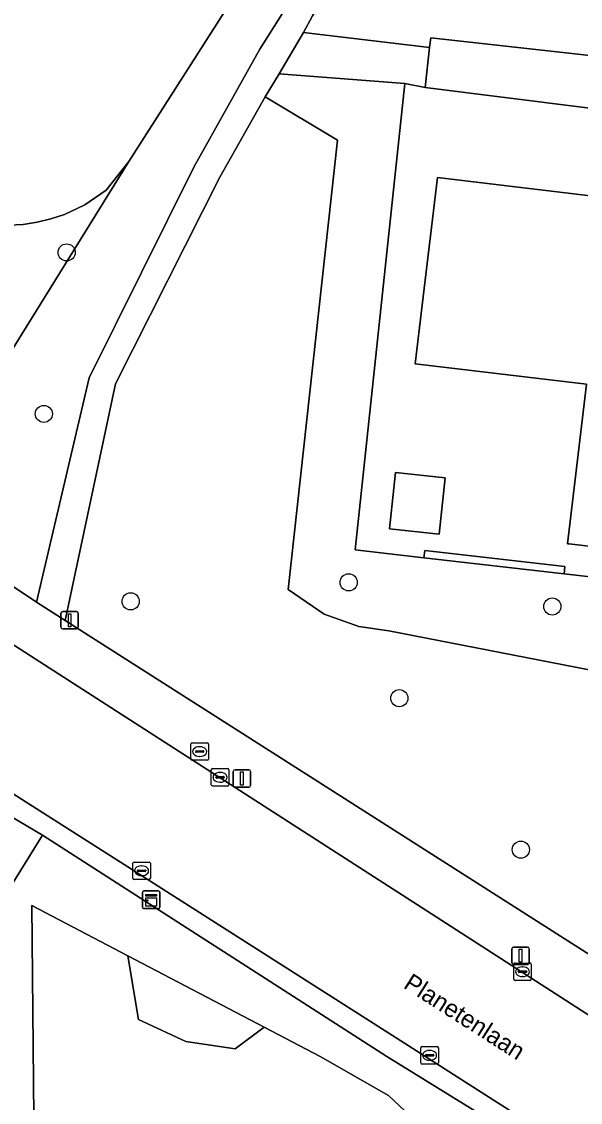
# Model space of a CAD drawing. Extents: x 162396 to 163643, y 386452 to 387406.
# Drawn here: x 162763.2 to 162795.2, y 386868.4 to 386930.2 of the extents above; entities that cross this region are included whole.
import ezdxf

# ---------------------------------------------------------------- set-up
doc = ezdxf.new("R2010")
doc.units = 0
for name, color, linetype in [('IMGEO_Afsluitpaal', 7, 'Continuous'), ('IMGEO_Boom', 7, 'Continuous'), ('IMGEO_Erf', 7, 'Continuous'), ('IMGEO_Groenvoorziening', 7, 'Continuous'), ('IMGEO_Haag', 7, 'Continuous'), ('IMGEO_Kast', 7, 'Continuous'), ('IMGEO_Kolk', 7, 'Continuous'), ('IMGEO_Lichtmast', 7, 'Continuous'), ('IMGEO_Meer_plas_ven_vijver', 7, 'Continuous'), ('IMGEO_Openbare_ruimte_label', 7, 'Continuous'), ('IMGEO_Pand', 7, 'Continuous'), ('IMGEO_Rijbaan_lokaal_gesloten', 7, 'Continuous'), ('IMGEO_Rioolput', 7, 'Continuous'), ('IMGEO_Voetpad_gesloten', 7, 'Continuous'), ('IMGEO_Voetpad_halfverhard', 7, 'Continuous'), ('IMGEO_Voetpad_open', 7, 'Continuous')]:
    doc.layers.add(name, color=color, linetype=linetype)

msp = doc.modelspace()

# ---------------------------------------------------------------- linework, layer by layer
at = {"layer": 'IMGEO_Afsluitpaal'}
for p, q in [((162765.499, 386895.606), (162765.499, 386896.406)), ((162765.499, 386896.406), (162765.499, 386895.606)), ((162765.599, 386896.506), (162766.389, 386896.506)), ((162766.389, 386896.506), (162765.599, 386896.506)), ((162766.489, 386896.406), (162766.489, 386895.606)), ((162766.489, 386895.606), (162766.489, 386896.406)), ((162766.389, 386895.506), (162765.599, 386895.506)), ((162765.599, 386895.506), (162766.389, 386895.506))]:
    msp.add_line(p, q, dxfattribs=at)
msp.add_lwpolyline([(162765.919, 386896.381), (162766.069, 386896.381), (162766.069, 386895.631), (162765.919, 386895.631), (162765.919, 386896.381)], dxfattribs=at)
for centre, start, end in [((162765.599, 386896.406), 90, 180), ((162765.599, 386896.406), 90, 180), ((162766.389, 386896.406), 0, 90), ((162766.389, 386896.406), 360, 90), ((162765.599, 386895.606), 180, 270), ((162765.599, 386895.606), 180, 270), ((162766.389, 386895.606), 270, 0), ((162766.389, 386895.606), 270, 0)]:
    msp.add_arc(centre, 0.1, start, end, dxfattribs=at)
at = {"layer": 'IMGEO_Boom'}
for centre in [(162765.821, 386917.046), (162764.516, 386907.809), (162781.941, 386898.173), (162769.48, 386897.087), (162793.578, 386896.79), (162784.833, 386891.55), (162791.779, 386882.885)]:
    msp.add_circle(centre, 0.489, dxfattribs=at)
at = {"layer": 'IMGEO_Erf'}
for points in [[(162845.362, 386895.67), (162826.392, 386897.805), (162827.899, 386911.454), (162807.866, 386913.527), (162808.925, 386923.64), (162786.308, 386926.481), (162785.145, 386926.702), (162782.318, 386900.035), (162786.244, 386899.582), (162786.295, 386900.001), (162794.294, 386899.088), (162794.254, 386898.657), (162802.049, 386897.757), (162802.451, 386897.712), (162801.311, 386887.204), (162813.918, 386885.683), (162813.87, 386885.286), (162800.871, 386886.854), (162800.855, 386886.61), (162821.896, 386883.1), (162821.137, 386877.022), (162842.733, 386874.373)], [(162834.608, 386886.23), (162823.428, 386887.562), (162823.189, 386885.557), (162822.872, 386885.595), (162823.045, 386887.048), (162814.57, 386888.058), (162815.926, 386899.438), (162804.505, 386900.8), (162804.315, 386899.207), (162794.543, 386900.371), (162794.438, 386900.384), (162795.525, 386909.507), (162785.739, 386910.672), (162786.138, 386914.018), (162787.008, 386921.322), (162806.715, 386918.974), (162805.543, 386909.139), (162818.238, 386907.626), (162818.053, 386906.071), (162819.962, 386905.844), (162820.164, 386907.539), (162825.402, 386906.915), (162824.246, 386897.211), (162844.258, 386894.826)]]:
    msp.add_lwpolyline(points, dxfattribs=at)
msp.add_lwpolyline([(162787.113, 386900.933), (162784.268, 386901.239), (162784.615, 386904.464), (162787.46, 386904.158)], close=True, dxfattribs=at)
at = {"layer": 'IMGEO_Groenvoorziening'}
for points in [[(162822.792, 386999.999), (162840.214, 387025.394), (162850.891, 387039.166), (162851.192, 387040.601), (162851.155, 387042.928), (162848.377, 387044.768), (162846.89, 387045.895), (162844.23, 387041.73), (162841.299, 387036.717), (162834.642, 387026.056), (162820.24, 387003.004), (162818.237, 387000.005), (162809.724, 386985.81), (162799.338, 386969.193), (162769.371, 386922.252), (162756.787, 386901.931), (162764.104, 386897.031), (162767.102, 386909.874), (162773.098, 386921.912), (162776.857, 386928.661), (162783.249, 386938.797)], [(162738.864, 386913.421), (162740.006, 386912.689), (162743.876, 386918.894), (162745.308, 386917.959), (162741.45, 386911.763), (162756.787, 386901.931), (162769.371, 386922.252), (162768.074, 386920.607), (162766.853, 386919.775), (162766.432, 386919.551), (162765.69, 386919.221), (162764.922, 386918.958), (162764.133, 386918.766), (162763.33, 386918.644), (162762.52, 386918.595), (162761.812, 386918.611), (162761.007, 386918.698), (162760.213, 386918.856), (162759.436, 386919.084), (162758.682, 386919.381), (162750.527, 386923.545), (162748.573, 386924.866), (162747.703, 386925.615)], [(162786.295, 386900.001), (162786.244, 386899.582), (162794.254, 386898.657), (162794.294, 386899.088)], [(162804.526, 386849.538), (162806.486, 386847.667), (162812.215, 386842.196), (162812.305, 386840.927), (162812.269, 386839.352), (162811.903, 386836.838), (162811.668, 386836.008), (162811.41, 386835.098), (162809.015, 386831.4), (162795.291, 386841.411), (162792.362, 386843.692), (162789.496, 386845.923), (162783.929, 386850.65), (162777.372, 386856.218), (162769.653, 386862.773), (162763.956, 386867.61), (162763.832, 386879.691), (162769.322, 386876.812), (162777.111, 386872.728), (162780.313, 386871.049), (162784.213, 386868.82), (162791.979, 386861.518), (162798.949, 386854.863)], [(162777.111, 386872.728), (162769.322, 386876.812), (162769.937, 386873.165), (162772.639, 386871.917), (162775.445, 386871.501)]]:
    msp.add_lwpolyline(points, close=True, dxfattribs=at)
for points in [[(162828.687, 386928.273), (162800.47, 386931.891), (162803.165, 386950.964), (162804.667, 386958.838), (162804.737, 386959.674), (162804.514, 386960.909), (162804.157, 386961.667), (162803.368, 386962.607), (162801.356, 386964.042), (162799.379, 386961.034), (162797.63, 386954.224), (162794.98, 386954.285), (162782.7, 386935.149), (162779.881, 386930.575), (162779.357, 386929.622), (162786.562, 386928.764), (162786.637, 386929.322), (162812.502, 386926.447), (162811.658, 386918.945), (162813.644, 386916.294), (162827.93, 386914.733)], [(162802.049, 386897.757), (162794.254, 386898.657), (162786.244, 386899.582), (162782.318, 386900.035), (162785.145, 386926.702), (162777.97, 386927.257), (162777.161, 386925.941), (162781.307, 386923.473), (162778.479, 386897.772), (162780.538, 386896.353), (162782.519, 386895.657), (162784.234, 386895.406), (162796.362, 386893.035)], [(162842.676, 386868.472), (162842.001, 386868.604), (162826.059, 386871.733), (162824.637, 386871.871), (162822.009, 386871.525), (162814.809, 386871.87), (162816.171, 386880.315), (162795.864, 386884.236), (162797.024, 386891.538), (162797.061, 386892.44), (162796.362, 386893.035), (162784.234, 386895.406), (162782.519, 386895.657), (162780.538, 386896.353), (162778.479, 386897.772), (162781.307, 386923.473), (162777.161, 386925.941), (162774.581, 386921.341), (162768.621, 386909.522), (162765.729, 386895.987), (162800.498, 386873.821), (162826.014, 386857.314), (162828.805, 386855.56)], [(162820.551, 386847.833), (162819.334, 386848.618), (162794.171, 386864.833), (162784.116, 386871.052), (162764.442, 386883.713), (162761.955, 386879.712), (162761.867, 386876.231), (162761.72, 386865.221)], [(162791.979, 386861.518), (162784.213, 386868.82), (162780.313, 386871.049), (162777.111, 386872.728), (162775.445, 386871.501), (162772.639, 386871.917), (162769.937, 386873.165), (162769.322, 386876.812), (162763.832, 386879.691), (162763.956, 386867.61)]]:
    msp.add_lwpolyline(points, dxfattribs=at)
at = {"layer": 'IMGEO_Haag'}
msp.add_lwpolyline([(162786.295, 386900.001), (162786.244, 386899.582), (162794.254, 386898.657), (162794.294, 386899.088)], close=True, dxfattribs=at)
at = {"layer": 'IMGEO_Kast'}
for p, q in [((162770.153, 386879.595), (162770.153, 386880.436)), ((162770.153, 386880.436), (162770.153, 386879.595)), ((162770.228, 386880.52), (162771.069, 386880.52)), ((162771.069, 386880.52), (162770.228, 386880.52)), ((162771.153, 386880.445), (162771.153, 386879.604)), ((162771.153, 386879.604), (162771.153, 386880.445)), ((162771.078, 386879.52), (162770.237, 386879.52)), ((162770.237, 386879.52), (162771.078, 386879.52))]:
    msp.add_line(p, q, dxfattribs=at)
for points in [[(162770.348, 386880.31), (162770.948, 386880.31), (162770.948, 386880.225), (162770.348, 386880.225), (162770.348, 386880.31)], [(162770.348, 386880.135), (162770.948, 386880.135), (162770.948, 386879.646), (162770.348, 386879.646), (162770.348, 386880.135)]]:
    msp.add_lwpolyline(points, dxfattribs=at)
msp.add_circle((162770.432, 386879.984), 0.0377, dxfattribs=at)
for centre, start, end in [((162770.231, 386880.442), 92.4484, 184.28452), ((162770.231, 386880.442), 92.4484, 184.28452), ((162771.075, 386880.442), 2.4484, 94.28452), ((162771.075, 386880.442), 2.4484, 94.28452), ((162770.231, 386879.598), 182.4484, 274.28452), ((162770.231, 386879.598), 182.4484, 274.28452), ((162771.075, 386879.598), 272.4484, 4.28452), ((162771.075, 386879.598), 272.4484, 4.28452)]:
    msp.add_arc(centre, 0.0779, start, end, dxfattribs=at)
at = {"layer": 'IMGEO_Kolk'}
for p, q in [((162774.09, 386886.598), (162774.09, 386887.45)), ((162774.165, 386887.524), (162775.017, 386887.524)), ((162775.091, 386887.45), (162775.091, 386886.598)), ((162774.349, 386887.018), (162774.349, 386887.03)), ((162774.787, 386886.981), (162774.389, 386886.981)), ((162774.392, 386887.067), (162774.79, 386887.067)), ((162774.578, 386887.304), (162774.603, 386887.304)), ((162774.833, 386887.03), (162774.833, 386887.018)), ((162775.017, 386886.524), (162774.165, 386886.524)), ((162774.601, 386886.744), (162774.576, 386886.744)), ((162769.606, 386881.251), (162769.606, 386882.103)), ((162769.681, 386882.177), (162770.533, 386882.177)), ((162770.094, 386881.957), (162770.119, 386881.957)), ((162770.607, 386882.103), (162770.607, 386881.251)), ((162769.865, 386881.671), (162769.865, 386881.683)), ((162770.303, 386881.634), (162769.905, 386881.634)), ((162769.908, 386881.72), (162770.306, 386881.72)), ((162770.117, 386881.397), (162770.092, 386881.397)), ((162770.349, 386881.683), (162770.349, 386881.671)), ((162770.533, 386881.177), (162769.681, 386881.177)), ((162791.375, 386875.475), (162791.375, 386876.327)), ((162791.45, 386876.401), (162792.302, 386876.401)), ((162792.376, 386876.327), (162792.376, 386875.475)), ((162791.634, 386875.895), (162791.634, 386875.907)), ((162792.072, 386875.858), (162791.674, 386875.858)), ((162791.677, 386875.944), (162792.075, 386875.944)), ((162791.863, 386876.181), (162791.888, 386876.181)), ((162792.118, 386875.907), (162792.118, 386875.895)), ((162792.302, 386875.401), (162791.45, 386875.401)), ((162791.886, 386875.621), (162791.861, 386875.621)), ((162786.064, 386870.696), (162786.064, 386871.548)), ((162786.139, 386871.622), (162786.991, 386871.622)), ((162786.552, 386871.402), (162786.577, 386871.402)), ((162787.065, 386871.548), (162787.065, 386870.696)), ((162786.323, 386871.116), (162786.323, 386871.128)), ((162786.761, 386871.079), (162786.363, 386871.079)), ((162786.366, 386871.165), (162786.764, 386871.165)), ((162786.575, 386870.842), (162786.55, 386870.842)), ((162786.807, 386871.128), (162786.807, 386871.116)), ((162786.991, 386870.622), (162786.139, 386870.622))]:
    msp.add_line(p, q, dxfattribs=at)
for points in [[(162774.09, 386886.598), (162774.09, 386887.45)], [(162774.165, 386887.524), (162775.017, 386887.524)], [(162775.091, 386887.45), (162775.091, 386886.598)], [(162775.017, 386886.524), (162774.165, 386886.524)], [(162769.606, 386881.251), (162769.606, 386882.103)], [(162769.681, 386882.177), (162770.533, 386882.177)], [(162770.607, 386882.103), (162770.607, 386881.251)], [(162770.533, 386881.177), (162769.681, 386881.177)], [(162791.375, 386875.475), (162791.375, 386876.327)], [(162791.45, 386876.401), (162792.302, 386876.401)], [(162792.376, 386876.327), (162792.376, 386875.475)], [(162792.302, 386875.401), (162791.45, 386875.401)], [(162786.064, 386870.696), (162786.064, 386871.548)], [(162786.139, 386871.622), (162786.991, 386871.622)], [(162787.065, 386871.548), (162787.065, 386870.696)], [(162786.991, 386870.622), (162786.139, 386870.622)]]:
    msp.add_lwpolyline(points, dxfattribs=at)
for centre, radius, start, end in [((162774.167, 386887.448), 0.0765, 91.55205, 178.44795), ((162774.167, 386887.448), 0.0765, 91.55205, 178.44795), ((162775.015, 386887.448), 0.0765, 1.55205, 88.44795), ((162775.015, 386887.448), 0.0765, 1.55205, 88.44795), ((162774.389, 386887.027), 0.0403, 85.87752, 175.75265), ((162774.386, 386887.017), 0.0366, 178.93798, 274.71019), ((162774.79, 386887.024), 0.043, 264.86636, 352.45326), ((162774.794, 386887.029), 0.0386, 1.73085, 96.63898), ((162774.167, 386886.6), 0.0765, 181.55205, 268.44795), ((162774.167, 386886.6), 0.0765, 181.55205, 268.44795), ((162775.015, 386886.6), 0.0765, 271.55205, 358.44795), ((162775.015, 386886.6), 0.0765, 271.55205, 358.44795), ((162769.683, 386882.101), 0.0765, 91.55205, 178.44795), ((162769.683, 386882.101), 0.0765, 91.55205, 178.44795), ((162770.531, 386882.101), 0.0765, 1.55205, 88.44795), ((162770.531, 386882.101), 0.0765, 1.55205, 88.44795), ((162769.905, 386881.68), 0.0403, 85.87752, 175.75265), ((162769.902, 386881.67), 0.0366, 178.93798, 274.71019), ((162770.306, 386881.677), 0.043, 264.86636, 352.45326), ((162770.31, 386881.682), 0.0386, 1.73085, 96.63898), ((162769.683, 386881.253), 0.0765, 181.55205, 268.44795), ((162769.683, 386881.253), 0.0765, 181.55205, 268.44795), ((162770.531, 386881.253), 0.0765, 271.55205, 358.44795), ((162770.531, 386881.253), 0.0765, 271.55205, 358.44795), ((162791.452, 386876.325), 0.0765, 91.55205, 178.44795), ((162791.452, 386876.325), 0.0765, 91.55205, 178.44795), ((162792.3, 386876.325), 0.0765, 1.55205, 88.44795), ((162792.3, 386876.325), 0.0765, 1.55205, 88.44795), ((162791.674, 386875.904), 0.0403, 85.87752, 175.75265), ((162791.671, 386875.894), 0.0366, 178.93798, 274.71019), ((162792.075, 386875.901), 0.043, 264.86636, 352.45326), ((162792.079, 386875.906), 0.0386, 1.73085, 96.63898), ((162791.452, 386875.477), 0.0765, 181.55205, 268.44795), ((162791.452, 386875.477), 0.0765, 181.55205, 268.44795), ((162792.3, 386875.477), 0.0765, 271.55205, 358.44795), ((162792.3, 386875.477), 0.0765, 271.55205, 358.44795), ((162786.141, 386871.546), 0.0765, 91.55205, 178.44795), ((162786.141, 386871.546), 0.0765, 91.55205, 178.44795), ((162786.989, 386871.546), 0.0765, 1.55205, 88.44795), ((162786.989, 386871.546), 0.0765, 1.55205, 88.44795), ((162786.363, 386871.125), 0.0403, 85.87752, 175.75265), ((162786.36, 386871.115), 0.0366, 178.93798, 274.71019), ((162786.764, 386871.122), 0.043, 264.86636, 352.45326), ((162786.768, 386871.127), 0.0386, 1.73085, 96.63898), ((162786.141, 386870.698), 0.0765, 181.55205, 268.44795), ((162786.141, 386870.698), 0.0765, 181.55205, 268.44795), ((162786.989, 386870.698), 0.0765, 271.55205, 358.44795), ((162786.989, 386870.698), 0.0765, 271.55205, 358.44795)]:
    msp.add_arc(centre, radius, start, end, dxfattribs=at)
for centre, major_axis, ratio, start_param, end_param in [((162774.577, 386887.024), (-0.387, 0.002), 0.722429, 4.712389, 7.853982), ((162774.602, 386887.024), (-0.39, 0.002), 0.717154, 1.570796, 4.712389), ((162770.093, 386881.677), (-0.387, 0.002), 0.722429, 4.712389, 7.853982), ((162770.118, 386881.677), (-0.39, 0.002), 0.717154, 1.570796, 4.712389), ((162791.862, 386875.901), (-0.387, 0.002), 0.722429, 4.712389, 7.853982), ((162791.887, 386875.901), (-0.39, 0.002), 0.717154, 1.570796, 4.712389), ((162786.551, 386871.122), (-0.387, 0.002), 0.722429, 4.712389, 7.853982), ((162786.576, 386871.122), (-0.39, 0.002), 0.717154, 1.570796, 4.712389)]:
    msp.add_ellipse(centre, major_axis=major_axis, ratio=ratio, start_param=start_param, end_param=end_param, dxfattribs=at)
at = {"layer": 'IMGEO_Lichtmast'}
for p, q in [((162775.447, 386887.451), (162776.237, 386887.451)), ((162776.237, 386887.451), (162775.447, 386887.451)), ((162775.347, 386886.551), (162775.347, 386887.351)), ((162775.347, 386887.351), (162775.347, 386886.551)), ((162776.337, 386887.351), (162776.337, 386886.551)), ((162776.337, 386886.551), (162776.337, 386887.351)), ((162776.237, 386886.451), (162775.447, 386886.451)), ((162775.447, 386886.451), (162776.237, 386886.451)), ((162791.268, 386876.416), (162791.268, 386877.216)), ((162791.268, 386877.216), (162791.268, 386876.416)), ((162791.368, 386877.316), (162792.158, 386877.316)), ((162792.158, 386877.316), (162791.368, 386877.316)), ((162792.258, 386877.216), (162792.258, 386876.416)), ((162792.258, 386876.416), (162792.258, 386877.216)), ((162792.158, 386876.316), (162791.368, 386876.316)), ((162791.368, 386876.316), (162792.158, 386876.316))]:
    msp.add_line(p, q, dxfattribs=at)
for points in [[(162775.767, 386887.326), (162775.917, 386887.326), (162775.917, 386886.576), (162775.767, 386886.576), (162775.767, 386887.326)], [(162791.688, 386877.191), (162791.838, 386877.191), (162791.838, 386876.441), (162791.688, 386876.441), (162791.688, 386877.191)]]:
    msp.add_lwpolyline(points, dxfattribs=at)
for centre, start, end in [((162775.447, 386887.351), 90, 180), ((162775.447, 386887.351), 90, 180), ((162776.237, 386887.351), 0, 90), ((162776.237, 386887.351), 360, 90), ((162775.447, 386886.551), 180, 270), ((162775.447, 386886.551), 180, 270), ((162776.237, 386886.551), 270, 0), ((162776.237, 386886.551), 270, 0), ((162791.368, 386877.216), 90, 180), ((162791.368, 386877.216), 90, 180), ((162792.158, 386877.216), 0, 90), ((162792.158, 386877.216), 360, 90), ((162791.368, 386876.416), 180, 270), ((162791.368, 386876.416), 180, 270), ((162792.158, 386876.416), 270, 0), ((162792.158, 386876.416), 270, 0)]:
    msp.add_arc(centre, 0.1, start, end, dxfattribs=at)
at = {"layer": 'IMGEO_Meer_plas_ven_vijver'}
msp.add_lwpolyline([(162918.383, 387161.062), (162747.703, 386925.615), (162748.573, 386924.866), (162750.527, 386923.545), (162758.682, 386919.381), (162759.436, 386919.084), (162760.213, 386918.856), (162761.007, 386918.698), (162761.812, 386918.611), (162762.52, 386918.595), (162763.33, 386918.644), (162764.133, 386918.766), (162764.922, 386918.958), (162765.69, 386919.221), (162766.432, 386919.551), (162766.853, 386919.775), (162768.074, 386920.607), (162769.371, 386922.252), (162799.338, 386969.193), (162809.724, 386985.81), (162818.237, 387000.005), (162820.24, 387003.004), (162834.642, 387026.056)], dxfattribs=at)
at = {"layer": 'IMGEO_Pand'}
for points in [[(162786.138, 386914.018), (162785.739, 386910.672), (162795.525, 386909.507), (162794.438, 386900.384), (162794.543, 386900.371), (162804.315, 386899.207), (162804.505, 386900.8), (162805.543, 386909.139), (162806.715, 386918.974), (162787.008, 386921.322)], [(162784.268, 386901.239), (162787.113, 386900.933), (162787.46, 386904.158), (162784.615, 386904.464)]]:
    msp.add_lwpolyline(points, close=True, dxfattribs=at)
at = {"layer": 'IMGEO_Rijbaan_lokaal_gesloten'}
msp.add_lwpolyline([(162732.519, 386905.283), (162732.519, 386905.283), (162745.396, 386897.065), (162757.506, 386889.413), (162768.474, 386882.429), (162784.448, 386872.261), (162817.434, 386851.158), (162819.973, 386849.537), (162823.672, 386855.407), (162820.21, 386857.595), (162786.675, 386879.214), (162755.243, 386899.437), (162737.16, 386911.071), (162735.144, 386908.29), (162732.519, 386905.283)], dxfattribs=at)
at = {"layer": 'IMGEO_Rioolput'}
for p, q in [((162772.924, 386888.069), (162772.924, 386888.921)), ((162772.999, 386888.995), (162773.851, 386888.995)), ((162773.412, 386888.775), (162773.437, 386888.775)), ((162773.925, 386888.921), (162773.925, 386888.069)), ((162773.183, 386888.489), (162773.183, 386888.501)), ((162773.621, 386888.452), (162773.223, 386888.452)), ((162773.226, 386888.538), (162773.624, 386888.538)), ((162773.435, 386888.215), (162773.41, 386888.215)), ((162773.667, 386888.501), (162773.667, 386888.489)), ((162773.851, 386887.995), (162772.999, 386887.995))]:
    msp.add_line(p, q, dxfattribs=at)
for points in [[(162772.924, 386888.069), (162772.924, 386888.921)], [(162772.999, 386888.995), (162773.851, 386888.995)], [(162773.925, 386888.921), (162773.925, 386888.069)], [(162773.851, 386887.995), (162772.999, 386887.995)]]:
    msp.add_lwpolyline(points, dxfattribs=at)
for centre, radius, start, end in [((162773.001, 386888.919), 0.0765, 91.55205, 178.44795), ((162773.001, 386888.919), 0.0765, 91.55205, 178.44795), ((162773.849, 386888.919), 0.0765, 1.55205, 88.44795), ((162773.849, 386888.919), 0.0765, 1.55205, 88.44795), ((162773.001, 386888.071), 0.0765, 181.55205, 268.44795), ((162773.001, 386888.071), 0.0765, 181.55205, 268.44795), ((162773.223, 386888.498), 0.0403, 85.87752, 175.75265), ((162773.22, 386888.488), 0.0366, 178.93798, 274.71019), ((162773.624, 386888.495), 0.043, 264.86636, 352.45326), ((162773.628, 386888.5), 0.0386, 1.73085, 96.63898), ((162773.849, 386888.071), 0.0765, 271.55205, 358.44795), ((162773.849, 386888.071), 0.0765, 271.55205, 358.44795)]:
    msp.add_arc(centre, radius, start, end, dxfattribs=at)
for centre, major_axis, ratio, start_param, end_param in [((162773.411, 386888.495), (-0.387, 0.002), 0.722429, 4.712389, 7.853982), ((162773.436, 386888.495), (-0.39, 0.002), 0.717154, 1.570796, 4.712389)]:
    msp.add_ellipse(centre, major_axis=major_axis, ratio=ratio, start_param=start_param, end_param=end_param, dxfattribs=at)
at = {"layer": 'IMGEO_Voetpad_gesloten'}
msp.add_lwpolyline([(162761.867, 386876.231), (162761.955, 386879.712), (162764.442, 386883.713), (162762.667, 386884.765), (162760.12, 386880.581), (162760.109, 386877.357), (162759.762, 386867.447), (162759.124, 386865.805), (162758.337, 386865.545), (162762.57, 386863.069)], dxfattribs=at)
at = {"layer": 'IMGEO_Voetpad_halfverhard'}
msp.add_lwpolyline([(162840.214, 387025.394), (162822.792, 386999.999), (162783.249, 386938.797), (162776.857, 386928.661), (162773.098, 386921.912), (162767.102, 386909.874), (162764.104, 386897.031), (162765.729, 386895.987), (162768.621, 386909.522), (162774.581, 386921.341), (162777.161, 386925.941), (162777.97, 386927.257), (162779.357, 386929.622), (162779.881, 386930.575), (162782.7, 386935.149), (162794.98, 386954.285), (162797.63, 386954.224), (162799.379, 386961.034), (162801.356, 386964.042), (162810.786, 386978.385), (162811.904, 386980.066), (162815.101, 386985.161), (162818.861, 386991.152), (162824.899, 387000)], dxfattribs=at)
at = {"layer": 'IMGEO_Voetpad_open'}
for points in [[(162786.562, 386928.764), (162779.357, 386929.622), (162777.97, 386927.257), (162785.145, 386926.702), (162786.308, 386926.481)], [(162812.502, 386926.447), (162786.637, 386929.322), (162786.562, 386928.764), (162786.308, 386926.481), (162808.925, 386923.64), (162807.866, 386913.527), (162827.899, 386911.454), (162828.398, 386914.682), (162827.93, 386914.733), (162813.644, 386916.294), (162811.658, 386918.945)]]:
    msp.add_lwpolyline(points, close=True, dxfattribs=at)
for points in [[(162738.864, 386913.421), (162737.16, 386911.071), (162755.243, 386899.437), (162786.675, 386879.214), (162820.21, 386857.595), (162823.672, 386855.407), (162826.505, 386853.58)], [(162832.21, 386853.42), (162828.805, 386855.56), (162826.014, 386857.314), (162800.498, 386873.821), (162765.729, 386895.987), (162764.104, 386897.031), (162756.787, 386901.931), (162741.45, 386911.763), (162740.006, 386912.689), (162738.864, 386913.421)], [(162821.993, 386848.16), (162819.973, 386849.537), (162817.434, 386851.158), (162784.448, 386872.261), (162768.474, 386882.429), (162757.506, 386889.413), (162745.396, 386897.065), (162732.519, 386905.283), (162732.519, 386905.283), (162731.775, 386904.431)], [(162731.775, 386904.431), (162740.429, 386898.928), (162749.873, 386892.893), (162758.066, 386887.745), (162758.12, 386887.711), (162759.613, 386886.773), (162759.659, 386886.742), (162762.667, 386884.765), (162764.442, 386883.713), (162784.116, 386871.052), (162794.171, 386864.833), (162819.334, 386848.618), (162820.551, 386847.833), (162820.846, 386847.701), (162824.327, 386845.024)]]:
    msp.add_lwpolyline(points, dxfattribs=at)

# ---------------------------------------------------------------- texts
at = {"layer": 'IMGEO_Openbare_ruimte_label'}
msp.add_text('Planetenlaan', height=1, rotation=327.40584, dxfattribs=at).set_placement((162785.015, 386875.016))

doc.saveas('drawing.dxf')
